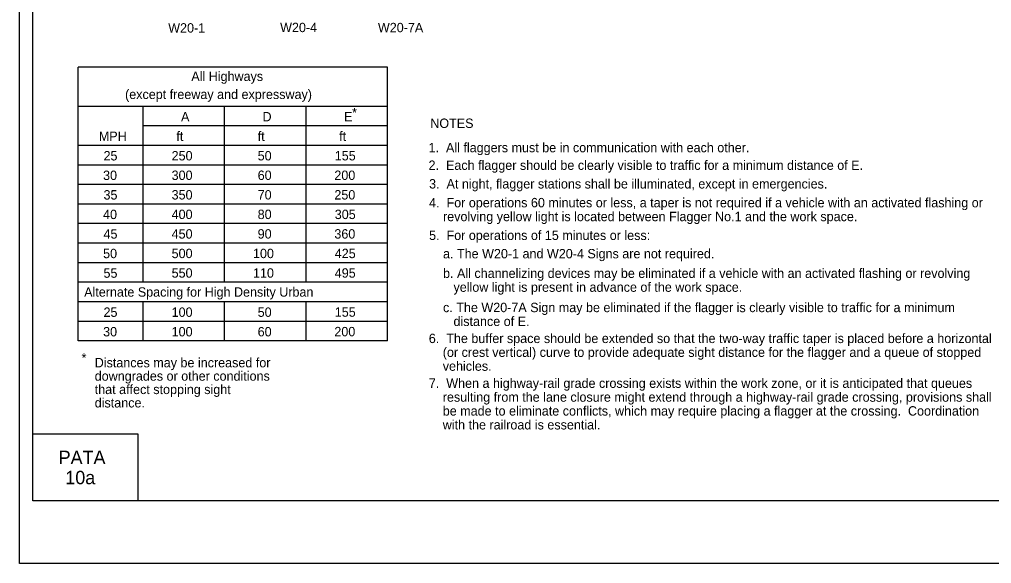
# Model space of a CAD drawing. Extents: x -14145 to -13662, y 30244 to 30661.
# Drawn here: x -13926.17 to -13904.42, y 30505.81 to 30517.97 of the extents above; entities that cross this region are included whole.
import ezdxf

# ---------------------------------------------------------------- set-up
doc = ezdxf.new("R2010")
doc.units = 0
for name, color, linetype in [('1', 7, 'Continuous'), ('10', 7, 'Continuous'), ('2', 7, 'Continuous'), ('3', 7, 'Continuous'), ('4', 7, 'Continuous'), ('61', 7, 'Continuous')]:
    doc.layers.add(name, color=color, linetype=linetype)

msp = doc.modelspace()

# ---------------------------------------------------------------- linework, layer by layer
at = {"layer": '1'}
for p, q in [((-13924.859, 30510.784), (-13924.859, 30516.903)), ((-13917.938, 30516.903), (-13924.859, 30516.903)), ((-13917.938, 30510.784), (-13917.938, 30516.903)), ((-13917.938, 30516.029), (-13924.86, 30516.029)), ((-13923.402, 30512.096), (-13923.402, 30516.029)), ((-13921.582, 30512.096), (-13921.582, 30516.029)), ((-13919.76, 30512.096), (-13919.76, 30516.029)), ((-13917.938, 30515.592), (-13923.402, 30515.592)), ((-13917.938, 30515.155), (-13924.86, 30515.155)), ((-13917.938, 30514.718), (-13924.86, 30514.718)), ((-13917.938, 30514.281), (-13924.86, 30514.281)), ((-13917.938, 30513.844), (-13924.86, 30513.844)), ((-13917.938, 30513.407), (-13924.86, 30513.407)), ((-13917.938, 30512.97), (-13924.86, 30512.97)), ((-13917.938, 30512.533), (-13924.86, 30512.533)), ((-13917.938, 30512.096), (-13924.86, 30512.096)), ((-13917.939, 30511.659), (-13924.86, 30511.659)), ((-13917.938, 30511.659), (-13924.86, 30511.659)), ((-13923.402, 30510.784), (-13923.402, 30511.659)), ((-13921.582, 30510.784), (-13921.582, 30511.659)), ((-13919.76, 30510.784), (-13919.76, 30511.659)), ((-13917.938, 30511.221), (-13924.86, 30511.221)), ((-13917.938, 30510.784), (-13924.859, 30510.784))]:
    msp.add_line(p, q, dxfattribs=at)
at = {"layer": '10'}
for p, q in [((-13925.874, 30507.207), (-13925.874, 30529.777)), ((-13925.874, 30508.707), (-13923.524, 30508.707)), ((-13923.524, 30508.707), (-13923.524, 30507.207)), ((-13894.422, 30507.207), (-13925.874, 30507.207))]:
    msp.add_line(p, q, dxfattribs=at)
at = {"layer": '61'}
msp.add_lwpolyline([(-13926.174, 30531.307), (-13893.174, 30531.307), (-13893.174, 30505.807), (-13926.174, 30505.807)], close=True, dxfattribs=at)

# ---------------------------------------------------------------- texts
at = {"layer": '2'}
for s, p in [('W20-1', (-13922.844, 30517.679)), ('W20-4', (-13920.34, 30517.689)), ('W20-7A', (-13918.151, 30517.687)), ('*', (-13918.73, 30515.785)), ('A', (-13922.557, 30515.694)), ('D', (-13920.734, 30515.694)), ('E', (-13918.91, 30515.694)), ('NOTES', (-13916.979, 30515.547)), ('MPH', (-13924.397, 30515.257)), ('ft', (-13922.662, 30515.257)), ('ft', (-13920.841, 30515.257)), ('ft', (-13919.019, 30515.257)), ('1.  All flaggers must be in communication with each other.', (-13917.018, 30515.003)), ('25', (-13924.292, 30514.82)), ('250', (-13922.768, 30514.821)), ('50', (-13920.842, 30514.821)), ('155', (-13919.117, 30514.821)), ('2.  Each flagger should be clearly visible to traffic for a minimum distance of E.', (-13917.018, 30514.609)), ('30', (-13924.302, 30514.383)), ('300', (-13922.768, 30514.384)), ('60', (-13920.842, 30514.384)), ('200', (-13919.126, 30514.384)), ('3.  At night, flagger stations shall be illuminated, except in emergencies.', (-13917.006, 30514.193)), ('35', (-13924.292, 30513.946)), ('350', (-13922.768, 30513.947)), ('70', (-13920.842, 30513.947)), ('250', (-13919.126, 30513.947)), ('4.  For operations 60 minutes or less, a taper is not required if a vehicle with an activated flashing or', (-13917.006, 30513.772)), ('40', (-13924.302, 30513.509)), ('400', (-13922.768, 30513.51)), ('80', (-13920.842, 30513.51)), ('305', (-13919.117, 30513.51)), ('    revolving yellow light is located between Flagger No.1 and the work space.', (-13917.006, 30513.462)), ('45', (-13924.292, 30513.072)), ('450', (-13922.768, 30513.073)), ('90', (-13920.842, 30513.073)), ('360', (-13919.126, 30513.073)), ('5.  For operations of 15 minutes or less:', (-13917.006, 30513.042)), ('50', (-13924.301, 30512.635)), ('500', (-13922.768, 30512.636)), ('100', (-13920.947, 30512.636)), ('425', (-13919.117, 30512.636)), ('    a. The W20-1 and W20-4 Signs are not required.', (-13917.006, 30512.631)), ('55', (-13924.292, 30512.197)), ('550', (-13922.768, 30512.199)), ('110', (-13920.947, 30512.199)), ('495', (-13919.117, 30512.199)), ('    b. All channelizing devices may be eliminated if a vehicle with an activated flashing or revolving', (-13917.006, 30512.193)), ('       yellow light is present in advance of the work space.', (-13917.006, 30511.883)), ('    c. The W20-7A Sign may be eliminated if the flagger is clearly visible to traffic for a minimum ', (-13917.006, 30511.428)), ('25', (-13924.292, 30511.323)), ('100', (-13922.768, 30511.323)), ('50', (-13920.842, 30511.323)), ('155', (-13919.117, 30511.325)), ('       distance of E.', (-13917.006, 30511.118)), ('30', (-13924.301, 30510.886)), ('100', (-13922.768, 30510.886)), ('60', (-13920.842, 30510.886)), ('200', (-13919.126, 30510.888)), ('6.  The buffer space should be extended so that the two-way traffic taper is placed before a horizontal', (-13917.012, 30510.737)), ('*', (-13924.783, 30510.301)), ('    (or crest vertical) curve to provide adequate sight distance for the flagger and a queue of stopped', (-13917.012, 30510.427)), ('Distances may be increased for ', (-13924.489, 30510.194)), ('    vehicles.', (-13917.012, 30510.117)), ('downgrades or other conditions ', (-13924.489, 30509.895)), ('7.  When a highway-rail grade crossing exists within the work zone, or it is anticipated that queues', (-13917.012, 30509.735)), ('that affect stopping sight ', (-13924.489, 30509.596)), ('    resulting from the lane closure might extend through a highway-rail grade crossing, provisions shall', (-13917.012, 30509.425)), ('distance.', (-13924.489, 30509.297)), ('    be made to eliminate conflicts, which may require placing a flagger at the crossing.  Coordination', (-13917.012, 30509.115)), ('    with the railroad is essential.', (-13917.012, 30508.805))]:
    msp.add_text(s, height=0.21, dxfattribs=at).set_placement(p)
at = {"layer": '3'}
for s, height, p in [('All Highways', 0.20979, (-13922.327, 30516.597)), ('(except freeway and expressway)', 0.21, (-13923.81, 30516.194)), ('Alternate Spacing for High Density Urban', 0.20979, (-13924.725, 30511.774))]:
    msp.add_text(s, height=height, dxfattribs=at).set_placement(p)
at = {"layer": '4'}
for s, p in [('PATA', (-13925.296, 30508.03)), ('10a', (-13925.147, 30507.58))]:
    msp.add_text(s, height=0.3, dxfattribs=at).set_placement(p)

doc.saveas('drawing.dxf')
